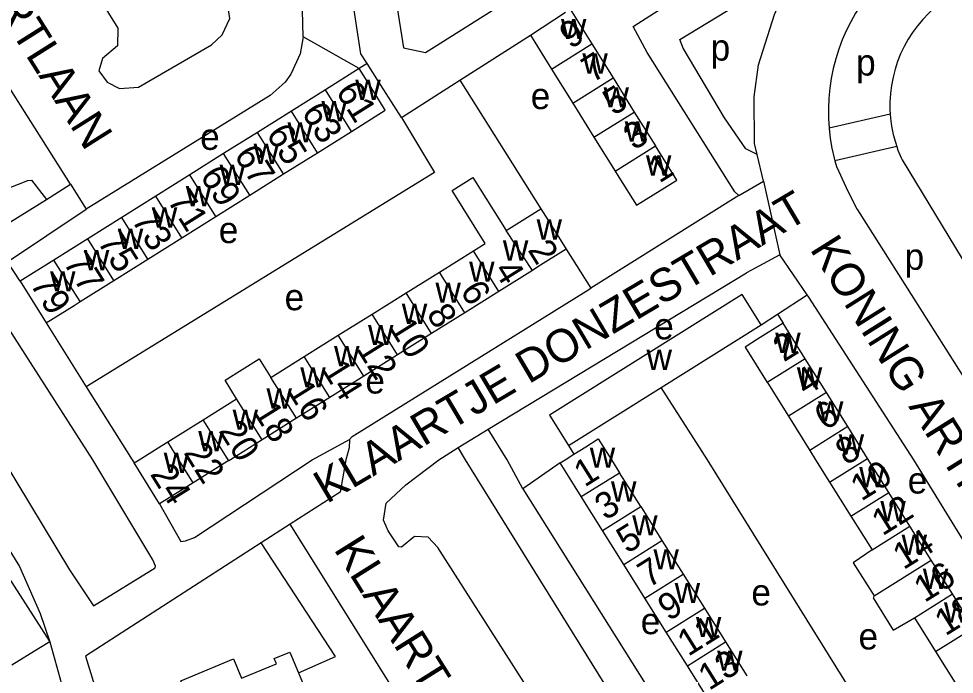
# Model space of a CAD drawing. Extents: x 159675 to 162108, y 386471 to 388472.
# Drawn here: x 160257.2 to 160399.4, y 387067.4 to 387167 of the extents above; entities that cross this region are included whole.
import ezdxf

# ---------------------------------------------------------------- set-up
doc = ezdxf.new("R2010")
doc.units = 0
for name, color, linetype in [('BLT_Basislijn', 7, 'Continuous'), ('BLT_Bebouwing', 7, 'Continuous'), ('BLT_Centroide', 7, 'Continuous'), ('BLT_Huisnummer', 7, 'Continuous'), ('BLT_Huisnummer_ tussenligend', 7, 'Continuous'), ('BLT_Onderverdeling_panden', 7, 'Continuous'), ('BLT_Straatnaam', 7, 'Continuous'), ('BLT_Vlakafsluiter', 7, 'Continuous')]:
    doc.layers.add(name, color=color, linetype=linetype)

msp = doc.modelspace()

# ---------------------------------------------------------------- linework, layer by layer
at = {"layer": 'BLT_Basislijn'}
for p, q in [((160265.05, 387141.86), (160217.82, 387216.31)), ((160308.94, 387159.42), (160300.43, 387164.24)), ((160310.14, 387160.16), (160308.94, 387159.42)), ((160324.22, 387157.65), (160336.54, 387138.13)), ((160389.65, 387152.46), (160380.34, 387150.35)), ((160390.64, 387147.56), (160381.21, 387145.42)), ((160381.21, 387145.42), (160381.46, 387144.53)), ((160261.4, 387139.54), (160265.05, 387141.86)), ((160265.05, 387141.86), (160267.45, 387138.04)), ((160366.63, 387140.12), (160344.14, 387126.07)), ((160384.65, 387137.94), (160410.01, 387097.95)), ((160340.39, 387131.97), (160344.14, 387126.07)), ((160328.54, 387104.64), (160367.8, 387128.41)), ((160372.49, 387122.09), (160377.03, 387125.03)), ((160370.01, 387120.49), (160372.49, 387122.09)), ((160372.49, 387122.09), (160373.37, 387120.73)), ((160261.35, 387120.78), (160267.44, 387111.09)), ((160323.96, 387101.85), (160328.54, 387104.64)), ((160340.75, 387102.14), (160341.56, 387100.85)), ((160339.45, 387099.53), (160333.82, 387095.59)), ((160298.46, 387090.22), (160294.05, 387087.36)), ((160294.05, 387087.36), (160267.35, 387070.17)), ((160261.92, 387072.36), (160260.26, 387071.33)), ((160261.92, 387072.36), (160266.48, 387056.01)), ((160260.26, 387071.33), (160256.14, 387068.77))]:
    msp.add_line(p, q, dxfattribs=at)
for points in [[(160250.03, 387201.25), (160272.27, 387165.55), (160272.21, 387162.84), (160269.91, 387160.96), (160269.38, 387159.08), (160270.61, 387157.33), (160272.52, 387156.37), (160275.39, 387156.61), (160286.47, 387163), (160288.1, 387164.51), (160289.27, 387167.04), (160281.17, 387220.89)], [(160184.88, 387195.63), (160220.54, 387139.55), (160222.79, 387136.44), (160228.68, 387129.86), (160235.04, 387123.54), (160236.95, 387124.4), (160261.4, 387139.54)], [(160366.63, 387140.12), (160366.01, 387140.7), (160352.71, 387161.85), (160350.55, 387165.8), (160375.82, 387182.01), (160378.16, 387183.16), (160380.43, 387180.62)], [(160392.64, 387176.7), (160391.41, 387175.8), (160390.24, 387174.83), (160389.11, 387173.8), (160388.04, 387172.71), (160387.03, 387171.57), (160386.08, 387170.38), (160385.2, 387169.14), (160384.38, 387167.85), (160383.63, 387166.53), (160382.95, 387165.16), (160382.34, 387163.77), (160381.81, 387162.34), (160381.35, 387160.88), (160380.97, 387159.41), (160380.67, 387157.91), (160380.44, 387156.41), (160380.3, 387154.89), (160380.23, 387153.37), (160380.25, 387151.84), (160380.34, 387150.35)], [(160300.43, 387164.24), (160300.31, 387168.23), (160299.35, 387174.59), (160299.21, 387175.46)], [(160369.43, 387146.36), (160367.71, 387147.21), (160364.45, 387151.95), (160358.17, 387162.52), (160357.66, 387163.81), (160373.26, 387173.35), (160374.78, 387173.89)], [(160369.43, 387146.36), (160369.02, 387148.02), (160368.94, 387155.1), (160369.6, 387159.99), (160372.06, 387167.6), (160374.78, 387173.89)], [(160402.84, 387172.31), (160401.67, 387171.87), (160400.53, 387171.36), (160399.43, 387170.78), (160398.37, 387170.12), (160397.34, 387169.4), (160396.37, 387168.62), (160395.45, 387167.77), (160394.59, 387166.87), (160393.78, 387165.92), (160393.04, 387164.91), (160392.36, 387163.86), (160391.76, 387162.77), (160391.22, 387161.64), (160390.76, 387160.48), (160390.37, 387159.3), (160390.06, 387158.09), (160389.82, 387156.86), (160389.67, 387155.62), (160389.6, 387154.37), (160389.6, 387153.12), (160389.65, 387152.46)], [(160300.43, 387164.24), (160299.97, 387161.63), (160298.54, 387158.57), (160297.68, 387157.36), (160295.38, 387155.34), (160267.45, 387138.04)], [(160315.34, 387151.98), (160320.38, 387143.62), (160267.44, 387111.09)], [(160389.65, 387152.46), (160389.69, 387151.88), (160389.85, 387150.64), (160390.09, 387149.41), (160390.42, 387148.21), (160390.64, 387147.56)], [(160380.34, 387150.35), (160380.52, 387148.81), (160380.77, 387147.3), (160381.1, 387145.82), (160381.21, 387145.42)], [(160390.64, 387147.56), (160390.81, 387147.02), (160391.29, 387145.87), (160391.44, 387145.53)], [(160366.63, 387140.12), (160370.36, 387142.33), (160369.43, 387146.36)], [(160381.46, 387144.53), (160382.96, 387141.33), (160384.53, 387138.17), (160384.65, 387137.94)], [(160391.44, 387145.53), (160412.74, 387110.46), (160449.71, 387115.95)], [(160242.27, 387136.02), (160258.58, 387142.42), (160259.15, 387142.46), (160261.4, 387139.54)], [(160257.39, 387127.1), (160255.49, 387130.04), (160267.45, 387138.04)], [(160377.03, 387125.03), (160372.84, 387131.12), (160367.8, 387128.41)], [(160268.57, 387077.83), (160277.92, 387083.57), (160277.95, 387083.84), (160277.57, 387084.81), (160268.45, 387100), (160250.74, 387127.58), (160250.2, 387127.92), (160240.2, 387121.85), (160238.53, 387120.66), (160238.42, 387119.75), (160249.5, 387108.54), (160254.84, 387100), (160264.92, 387083.25), (160268.57, 387077.83)], [(160307.44, 387103.05), (160307.87, 387103.55), (160343.4, 387125.61), (160344.14, 387126.07)], [(160419.78, 387056.83), (160393.22, 387100), (160377.27, 387124.67), (160377.03, 387125.03)], [(160234.04, 387116.48), (160239.35, 387111.26), (160244.57, 387103.88), (160253.28, 387090.17), (160257.32, 387083.77), (160260.47, 387076.63), (160261.92, 387072.36)], [(160267.44, 387111.09), (160274.41, 387100), (160274.72, 387099.51)], [(160397.71, 387042.31), (160361.89, 387100), (160354.83, 387110.97)], [(160333.82, 387095.59), (160331.43, 387100), (160328.54, 387104.64)], [(160278.6, 387093.29), (160281.82, 387087.57), (160282.53, 387087.68), (160283.9, 387088.2), (160301.78, 387100), (160307.44, 387103.05)], [(160307.44, 387103.05), (160307.43, 387101.81), (160306.88, 387100), (160306.05, 387095.07), (160298.46, 387090.22)], [(160356.18, 387021.2), (160355.13, 387022.5), (160354.47, 387023.93), (160354.36, 387026.72), (160354.65, 387027.7), (160356.86, 387029.97), (160356.7, 387030.61), (160320.9, 387086.69), (160319.39, 387088.25), (160317.34, 387088.36), (160315.35, 387086.74), (160314.97, 387086.79), (160313.32, 387089.18), (160312.6, 387090.8), (160313.05, 387093.38), (160316.02, 387096.18), (160321.03, 387100), (160323.96, 387101.85)], [(160356.18, 387021.2), (160368.34, 387028.96), (160368.66, 387029.53), (160368.41, 387030.25), (160325.11, 387100), (160323.96, 387101.85)], [(160333.82, 387095.59), (160375.34, 387029.53), (160375.25, 387028.32), (160335.68, 387003.2), (160335.77, 387002.42), (160337.31, 386999.73)], [(160356.18, 387021.2), (160347.15, 387015.5), (160345.5, 387014.96), (160298.46, 387090.22)], [(160252.29, 387087.29), (160261.92, 387072.36)], [(160299.72, 387067.62), (160305.33, 387070.1), (160294.05, 387087.36)], [(160267.35, 387070.17), (160276.07, 387041.83), (160278.28, 387036.21), (160280.63, 387032.32), (160284.87, 387027.87), (160291.23, 387022.92), (160295.86, 387018.28), (160302.57, 387010.6)]]:
    msp.add_lwpolyline(points, dxfattribs=at)
at = {"layer": 'BLT_Bebouwing'}
for p, q in [((160334.95, 387164.5), (160340.26, 387167.96)), ((160341.01, 387168.43), (160344.3, 387163.15)), ((160324.22, 387157.65), (160334.95, 387164.5)), ((160334.95, 387164.5), (160338.17, 387159.33)), ((160344.3, 387163.15), (160347.52, 387157.98)), ((160308.94, 387159.42), (160303.79, 387156.19)), ((160338.17, 387159.33), (160341.39, 387154.16)), ((160315.34, 387151.98), (160324.22, 387157.65)), ((160347.52, 387157.98), (160350.74, 387152.81)), ((160303.79, 387156.19), (160298.64, 387152.96)), ((160298.64, 387152.96), (160293.48, 387149.72)), ((160341.39, 387154.16), (160344.61, 387148.99)), ((160350.74, 387152.81), (160353.96, 387147.65)), ((160293.48, 387149.72), (160288.32, 387146.49)), ((160302.6, 387146.63), (160307.75, 387149.86)), ((160344.61, 387148.99), (160347.83, 387143.82)), ((160288.32, 387146.49), (160283.17, 387143.26)), ((160297.44, 387143.4), (160302.6, 387146.63)), ((160283.17, 387143.26), (160278.01, 387140.03)), ((160292.29, 387140.17), (160297.44, 387143.4)), ((160287.13, 387136.94), (160292.29, 387140.17)), ((160278.01, 387140.03), (160272.86, 387136.8)), ((160331.26, 387134.84), (160336.54, 387138.13)), ((160272.86, 387136.8), (160267.7, 387133.57)), ((160281.97, 387133.71), (160287.13, 387136.94)), ((160267.7, 387133.57), (160262.54, 387130.33)), ((160276.82, 387130.47), (160281.97, 387133.71)), ((160321.12, 387128.5), (160326.3, 387131.73)), ((160262.54, 387130.33), (160257.39, 387127.1)), ((160271.66, 387127.24), (160276.82, 387130.47)), ((160335.25, 387128.76), (160330.15, 387125.56)), ((160316.06, 387125.34), (160321.12, 387128.5)), ((160257.39, 387127.1), (160261.35, 387120.78)), ((160266.51, 387124.01), (160271.66, 387127.24)), ((160310.9, 387122.12), (160316.06, 387125.34)), ((160330.15, 387125.56), (160324.98, 387122.32)), ((160305.75, 387118.9), (160310.9, 387122.12)), ((160324.98, 387122.32), (160319.92, 387119.15)), ((160354.83, 387110.97), (160370.01, 387120.49)), ((160376.73, 387115.34), (160373.37, 387120.73)), ((160300.58, 387115.67), (160305.75, 387118.9)), ((160319.92, 387119.15), (160314.77, 387115.92)), ((160314.77, 387115.92), (160309.62, 387112.7)), ((160295.52, 387112.5), (160300.58, 387115.67)), ((160379.93, 387110.21), (160376.73, 387115.34)), ((160309.62, 387112.7), (160304.46, 387109.46)), ((160340.75, 387102.14), (160354.83, 387110.97)), ((160285.21, 387106.06), (160290.29, 387109.24)), ((160304.46, 387109.46), (160299.4, 387106.29)), ((160383.17, 387105.02), (160379.93, 387110.21)), ((160279.83, 387102.7), (160285.21, 387106.06)), ((160299.4, 387106.29), (160294.18, 387103.02)), ((160374.16, 387106.61), (160377.4, 387101.42)), ((160386.18, 387100.18), (160383.17, 387105.02)), ((160278.6, 387093.29), (160274.72, 387099.51)), ((160288.89, 387099.71), (160283.72, 387096.48)), ((160289.1, 387099.84), (160288.89, 387099.71)), ((160389.41, 387095.04), (160386.18, 387100.18)), ((160380.43, 387096.58), (160383.65, 387091.43)), ((160392.63, 387089.9), (160389.41, 387095.04)), ((160345.9, 387089.24), (160342.68, 387094.39)), ((160351.72, 387092.89), (160354.94, 387087.75)), ((160383.65, 387091.43), (160386.87, 387086.29)), ((160349.13, 387084.1), (160345.9, 387089.24)), ((160395.86, 387084.76), (160392.63, 387089.9)), ((160354.94, 387087.75), (160358.17, 387082.61)), ((160399.09, 387079.62), (160395.86, 387084.76)), ((160352.36, 387078.96), (160349.13, 387084.1)), ((160358.17, 387082.61), (160361.4, 387077.47)), ((160355.58, 387073.82), (160352.36, 387078.96)), ((160402.31, 387074.48), (160399.09, 387079.62)), ((160361.4, 387077.47), (160364.62, 387072.33)), ((160393.31, 387075.99), (160396.53, 387070.85)), ((160358.81, 387068.68), (160355.58, 387073.82)), ((160364.62, 387072.33), (160367.85, 387067.19)), ((160362.03, 387063.54), (160358.81, 387068.68))]:
    msp.add_line(p, q, dxfattribs=at)
for points in [[(160306.88, 387176.61), (160313.29, 387177.63), (160315.65, 387162.58), (160319.02, 387161.83), (160334.18, 387171.47), (160329.18, 387179.33), (160330.67, 387180.28)], [(160310.14, 387160.16), (160309.18, 387161.66), (160306.88, 387176.61)], [(160315.34, 387151.98), (160311.86, 387157.44), (160310.14, 387160.16)], [(160307.75, 387149.86), (160312.9, 387153.09), (160311.6, 387155.18), (160308.94, 387159.42)], [(160347.83, 387143.82), (160348.41, 387142.9), (160351.05, 387138.65), (160357.18, 387142.48), (160353.96, 387147.65)], [(160326.3, 387131.73), (160328.1, 387132.86), (160323.05, 387140.91), (160326.21, 387142.89), (160331.26, 387134.84)], [(160336.54, 387138.13), (160337.93, 387135.89), (160340.39, 387131.97)], [(160340.39, 387131.97), (160336.08, 387129.28), (160335.25, 387128.76)], [(160370.01, 387120.49), (160367.11, 387125.11), (160337.85, 387106.77), (160340.75, 387102.14)], [(160261.35, 387120.78), (160265.59, 387123.43), (160266.51, 387124.01)], [(160373.37, 387120.73), (160369.47, 387118.29), (160367.59, 387117.12), (160370.95, 387111.73)], [(160290.29, 387109.24), (160288.56, 387112.08), (160293.72, 387115.3), (160295.52, 387112.5)], [(160370.95, 387111.73), (160371.02, 387111.62), (160374.16, 387106.61)], [(160341.56, 387100.85), (160343.37, 387101.98), (160345.27, 387103.17), (160347.26, 387100), (160348.49, 387098.03)], [(160274.72, 387099.51), (160275.51, 387100), (160278.96, 387102.16), (160279.83, 387102.7)], [(160294.18, 387103.02), (160289.36, 387100), (160289.1, 387099.84)], [(160339.45, 387099.53), (160340.21, 387100), (160341.56, 387100.85)], [(160377.4, 387101.42), (160378.29, 387100), (160380.43, 387096.58)], [(160342.68, 387094.39), (160341.74, 387095.88), (160339.45, 387099.53)], [(160351.72, 387092.89), (160349.31, 387096.73), (160348.49, 387098.03)], [(160283.72, 387096.48), (160282.33, 387095.62), (160278.6, 387093.29)], [(160386.87, 387086.29), (160384.02, 387084.32), (160387.21, 387079.33)], [(160387.21, 387079.33), (160387.02, 387079.01), (160390.08, 387074.12), (160393.31, 387075.99)], [(160289.81, 387069.78), (160291.05, 387066.84), (160296.36, 387068.99), (160296.02, 387069.79), (160298.41, 387070.78)], [(160298.41, 387070.78), (160299.72, 387067.62)], [(160396.53, 387070.85), (160399.75, 387065.7)], [(160322, 387008.71), (160319.16, 387007.5), (160317.79, 387010.73), (160310.61, 387007.68), (160288.65, 387059.5), (160285.32, 387058.09), (160281.8, 387066.39), (160289.81, 387069.78)], [(160299.72, 387067.62), (160300.94, 387064.69)]]:
    msp.add_lwpolyline(points, dxfattribs=at)
at = {"layer": 'BLT_Onderverdeling_panden'}
for p, q in [((160338.17, 387159.33), (160344.3, 387163.15)), ((160341.39, 387154.16), (160347.52, 387157.98)), ((160307.75, 387149.86), (160303.79, 387156.19)), ((160302.6, 387146.63), (160298.64, 387152.96)), ((160344.61, 387148.99), (160350.74, 387152.81)), ((160297.44, 387143.4), (160293.48, 387149.72)), ((160347.83, 387143.82), (160353.96, 387147.65)), ((160292.29, 387140.17), (160288.32, 387146.49)), ((160287.13, 387136.94), (160283.17, 387143.26)), ((160281.97, 387133.71), (160278.01, 387140.03)), ((160276.82, 387130.47), (160272.86, 387136.8)), ((160335.25, 387128.76), (160331.26, 387134.84)), ((160271.66, 387127.24), (160267.7, 387133.57)), ((160330.15, 387125.56), (160326.3, 387131.73)), ((160266.51, 387124.01), (160262.54, 387130.33)), ((160324.98, 387122.32), (160321.12, 387128.5)), ((160319.92, 387119.15), (160316.06, 387125.34)), ((160314.77, 387115.92), (160310.9, 387122.12)), ((160309.62, 387112.7), (160305.75, 387118.9)), ((160304.46, 387109.46), (160300.58, 387115.67)), ((160376.73, 387115.34), (160370.95, 387111.73)), ((160299.4, 387106.29), (160295.52, 387112.5)), ((160294.18, 387103.02), (160290.29, 387109.24)), ((160379.93, 387110.21), (160374.16, 387106.61)), ((160289.1, 387099.84), (160285.21, 387106.06)), ((160383.17, 387105.02), (160377.4, 387101.42)), ((160380.43, 387096.58), (160386.18, 387100.18)), ((160342.68, 387094.39), (160348.49, 387098.03)), ((160383.65, 387091.43), (160389.41, 387095.04)), ((160345.9, 387089.24), (160351.72, 387092.89)), ((160386.87, 387086.29), (160392.63, 387089.9)), ((160349.13, 387084.1), (160354.94, 387087.75)), ((160387.21, 387079.33), (160395.86, 387084.76)), ((160352.36, 387078.96), (160358.17, 387082.61)), ((160393.31, 387075.99), (160399.09, 387079.62)), ((160355.58, 387073.82), (160361.4, 387077.47)), ((160396.53, 387070.85), (160402.31, 387074.48)), ((160358.81, 387068.68), (160364.62, 387072.33))]:
    msp.add_line(p, q, dxfattribs=at)
msp.add_lwpolyline([(160283.72, 387096.48), (160281.52, 387100), (160279.83, 387102.7)], dxfattribs=at)
at = {"layer": 'BLT_Vlakafsluiter'}
msp.add_line((160370.36, 387142.33), (160372.84, 387131.12), dxfattribs=at)

# ---------------------------------------------------------------- texts
at = {"layer": 'BLT_Centroide'}
for s, p in [('w', (160339.59, 387163.88)), ('p', (160362.34, 387160.62)), ('w', (160342.85, 387158.66)), ('p', (160384.45, 387158.35)), ('w', (160308.34, 387154.64)), ('e', (160335, 387153.25)), ('w', (160346.07, 387153.5)), ('w', (160303.19, 387151.41)), ('e', (160284.76, 387147.06)), ('w', (160298.03, 387148.19)), ('w', (160349.29, 387148.31)), ('w', (160292.88, 387144.94)), ('w', (160352.51, 387143.16)), ('w', (160287.72, 387141.72)), ('w', (160282.58, 387138.48)), ('w', (160277.42, 387135.25)), ('e', (160287.59, 387132.9)), ('w', (160335.89, 387133.44)), ('w', (160272.25, 387132.03)), ('w', (160330.77, 387130.23)), ('w', (160267.09, 387128.78)), ('p', (160391.82, 387128.85)), ('w', (160325.64, 387127.02)), ('w', (160261.95, 387125.56)), ('w', (160320.52, 387123.83)), ('e', (160297.59, 387122.7)), ('w', (160315.41, 387120.62)), ('w', (160310.27, 387117.41)), ('e', (160353.77, 387118.28)), ('w', (160372.16, 387116.22)), ('w', (160305.11, 387114.19)), ('w', (160352.6, 387113.62)), ('w', (160299.98, 387110.97)), ('e', (160309.86, 387110.05)), ('w', (160375.44, 387110.97)), ('w', (160294.84, 387107.77)), ('w', (160378.66, 387105.81)), ('w', (160289.69, 387104.55)), ('w', (160284.47, 387101.27)), ('w', (160381.8, 387100.78)), ('w', (160343.97, 387098.78)), ('w', (160279.22, 387098)), ('w', (160384.92, 387095.81)), ('e', (160392.29, 387094.86)), ('w', (160347.2, 387093.62)), ('w', (160388.14, 387090.66)), ('w', (160350.42, 387088.5)), ('w', (160391.37, 387085.53)), ('w', (160353.65, 387083.34)), ('w', (160394.59, 387080.38)), ('w', (160356.88, 387078.22)), ('e', (160368.53, 387077.86)), ('w', (160397.81, 387075.25)), ('e', (160351.72, 387073.5)), ('w', (160360.1, 387073.06)), ('e', (160384.82, 387071.18)), ('w', (160363.33, 387067.94))]:
    msp.add_text(s, height=4, dxfattribs=at).set_placement(p)
at = {"layer": 'BLT_Huisnummer'}
for s, rotation, p in [('9', 31.9222, (160341.02, 387162.29)), ('61', 302.077, (160305.27, 387155.94)), ('5', 31.9222, (160347.59, 387152.17)), ('65', 302.077, (160294.7, 387149.46)), ('1', 31.9222, (160354.53, 387141.92)), ('69', 302.077, (160284.65, 387143.12)), ('73', 302.077, (160274.24, 387136.41)), ('2', 301.9887, (160334.46, 387131.86)), ('79', 302.077, (160258.81, 387126.7)), ('6', 301.9887, (160324.18, 387125.65)), ('10', 301.9887, (160313.38, 387120.08)), ('2', 31.9609, (160373.46, 387114.76)), ('14', 301.9887, (160303.19, 387113.65)), ('6', 31.9609, (160379.73, 387104.35)), ('18', 301.9887, (160292.72, 387107.29)), ('24', 301.9887, (160277.07, 387097.82)), ('1', 32.101, (160343.19, 387095.75)), ('10', 31.9609, (160385.23, 387093.61)), ('5', 32.101, (160349.67, 387085.65)), ('14', 31.9609, (160391.65, 387083.2)), ('9', 32.101, (160355.95, 387075.4)), ('18', 31.9609, (160398.02, 387073.14)), ('13', 32.101, (160362.1, 387064.86))]:
    msp.add_text(s, height=4, rotation=rotation, dxfattribs=at).set_placement(p)
at = {"layer": 'BLT_Huisnummer_ tussenligend'}
for s, rotation, p in [('7', 31.9197, (160344.35, 387157.15)), ('63', 302.077, (160300.07, 387152.75)), ('3', 31.9197, (160350.7, 387146.91)), ('67', 302.077, (160289.82, 387146.27)), ('71', 302.077, (160279.68, 387139.38)), ('75', 302.077, (160269.06, 387133.12)), ('77', 302.077, (160263.86, 387129.96)), ('4', 301.9863, (160329.29, 387128.78)), ('8', 301.9863, (160319.06, 387122.14)), ('12', 301.9863, (160308.42, 387116.86)), ('4', 31.9547, (160376.79, 387109.57)), ('16', 301.9863, (160297.89, 387110.52)), ('20', 301.9863, (160287.49, 387104.41)), ('8', 31.9547, (160382.94, 387099.05)), ('22', 301.9863, (160282.17, 387101.08)), ('3', 32.101, (160346.36, 387090.7)), ('12', 31.9547, (160388.45, 387088.34)), ('7', 32.101, (160352.9, 387080.44)), ('16', 31.9547, (160394.85, 387078.22)), ('11', 32.101, (160358.93, 387070.04))]:
    msp.add_text(s, height=4, rotation=rotation, dxfattribs=at).set_placement(p)
at = {"layer": 'BLT_Straatnaam'}
for s, rotation, p in [('REINAERTLAAN', 302.2034, (160240.13, 387190.1)), ('KLAARTJE DONZESTRAAT', 30.6391, (160303.99, 387093.25)), ('KONING ARTHURLAAN', 302.1158, (160377.33, 387132)), ('KLAARTJE DONZESTRAAT', 302.0716, (160304.98, 387086.42))]:
    msp.add_text(s, height=5, rotation=rotation, dxfattribs=at).set_placement(p)

doc.saveas('drawing.dxf')
